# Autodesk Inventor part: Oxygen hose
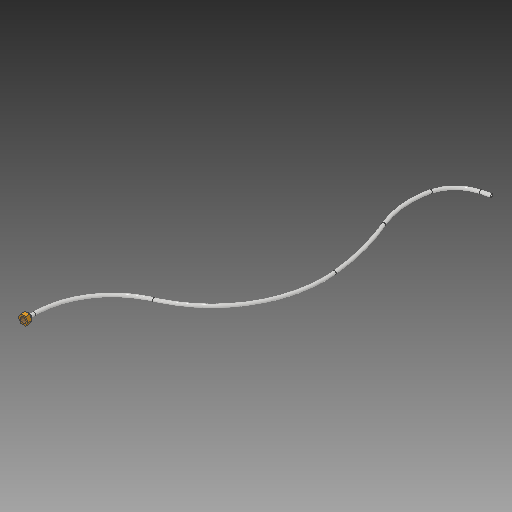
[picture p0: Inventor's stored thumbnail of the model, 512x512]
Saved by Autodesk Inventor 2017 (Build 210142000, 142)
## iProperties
Created: 2020-03
Part Number: Oxygen hose
Material: Generic
Document SubType Name: Modeling
Designer: user
Density: 1 g/cm^3
Appearance: Default
Mass: 13.5383 g
Surface Area: 387.588 cm^2
Volume: 13.5383 cm^3
Author: user
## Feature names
1. Sweep1
2. Extrusion1
3. Extrusion2
## Parameters: d5 = 67.98759 mm, d6 = 329.75314 mm, d7 = 19.33825 mm, d8 = 5.10217 mm, d10 = 15 mm, d11 = 607.574 mm, d12 = 6 mm, d13 = 7.25 mm, d14 = 0, d15 = 0, d16 = 12.7 mm, d17 = 21 mm, d18 = 9 mm, d19 = 0, d21 = 0, d22 = 4 mm, d23 = 0
